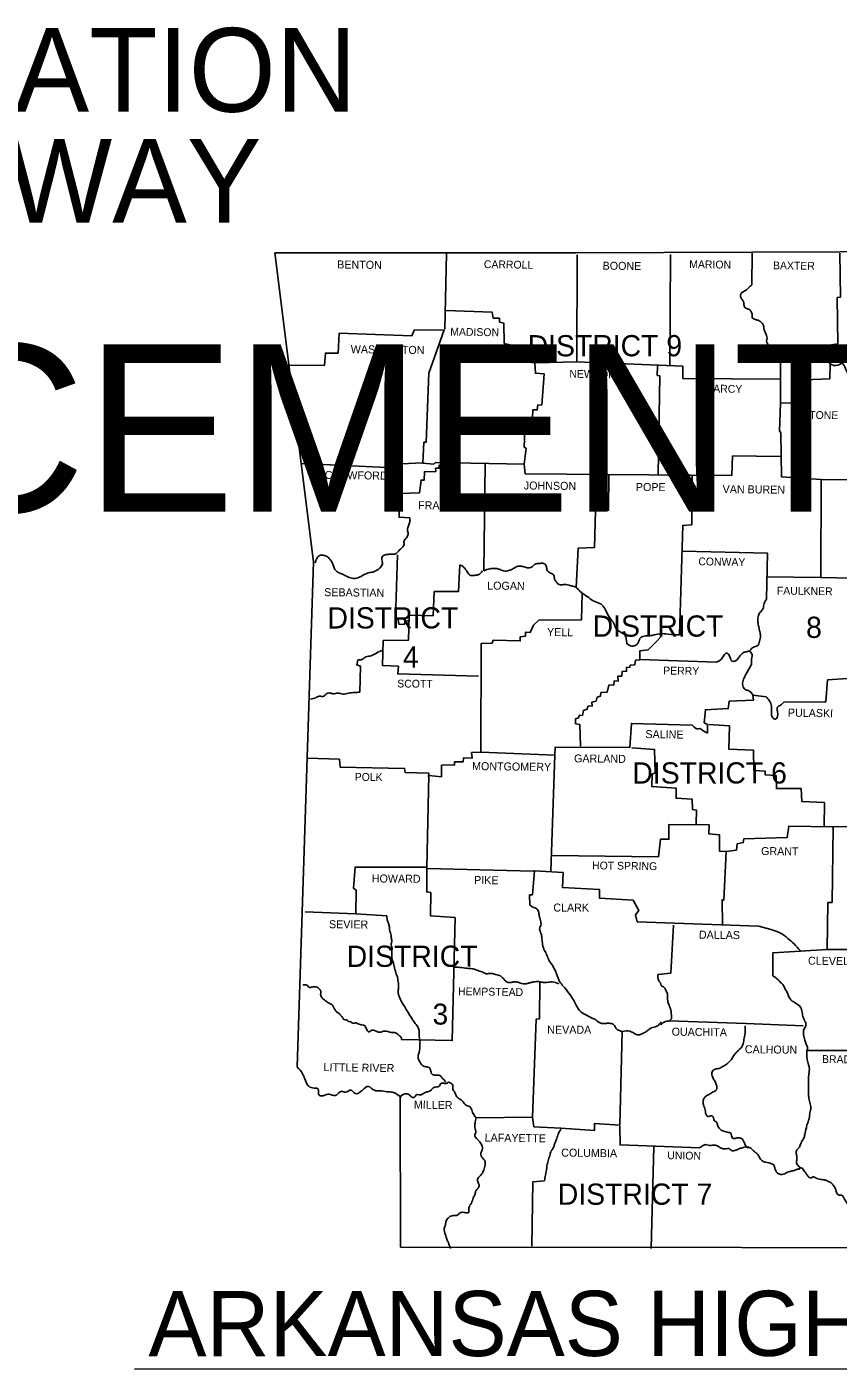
# Model space of a CAD drawing. Extents: x 2520745 to 2582119, y -1491628 to -1461664.
# Drawn here: x 2555441 to 2561979, y -1472575 to -1461753 of the extents above; entities that cross this region are included whole.
import ezdxf

# ---------------------------------------------------------------- set-up
doc = ezdxf.new("R2010")
doc.units = 0
doc.layers.add('R_Draft', color=7, linetype='Continuous')

msp = doc.modelspace()

# ---------------------------------------------------------------- linework, layer by layer
at = {"layer": 'R_Draft'}
msp.add_line((2556309, -1472575), (2566227, -1472569), dxfattribs=at)
for points in [[(2557440, -1463574), (2559865, -1463574), (2561994, -1463568), (2564505, -1463528), (2565669, -1463500)], [(2557619, -1470137), (2557752, -1466067), (2557440, -1463574)], [(2558824, -1463582), (2558811, -1464190)], [(2558821, -1464041), (2559190, -1464053), (2559199, -1464101), (2559250, -1464103), (2559249, -1464133), (2559285, -1464142), (2559288, -1464305), (2559335, -1464316), (2559338, -1464380), (2559404, -1464389), (2559407, -1464449), (2559537, -1464462), (2559873, -1464455), (2559876, -1463592)], [(2560627, -1463589), (2560623, -1464480)], [(2561287, -1463578), (2561284, -1463834)], [(2561541, -1467197), (2561879, -1467196), (2561894, -1467019), (2562095, -1467003), (2562094, -1466199), (2561839, -1466192), (2561843, -1465402), (2561522, -1465381), (2561518, -1465027), (2561507, -1465009), (2561516, -1464787), (2561702, -1464781), (2561709, -1464598), (2561913, -1464590), (2561916, -1464471), (2561880, -1464425), (2561871, -1464325), (2561976, -1464309), (2561971, -1463936), (2561997, -1463934), (2561994, -1463577)], [(2559457, -1465358), (2559449, -1465279), (2558734, -1465265), (2558720, -1465279), (2558632, -1465272), (2558641, -1465103), (2558659, -1465102), (2558682, -1464545), (2558804, -1464197), (2558562, -1464199), (2558544, -1464244), (2557959, -1464223), (2557950, -1464384), (2557847, -1464384), (2557839, -1464483), (2557559, -1464482)], [(2559534, -1464465), (2559540, -1464546), (2559609, -1464551), (2559591, -1464803), (2559560, -1464801), (2559554, -1464842), (2559518, -1464842), (2559516, -1464911), (2559494, -1464912), (2559487, -1465001), (2559454, -1465006), (2559449, -1465141), (2559464, -1465151), (2559449, -1465279)], [(2559873, -1464455), (2560728, -1464490), (2560727, -1464588), (2561511, -1464593)], [(2561516, -1464787), (2561514, -1464449)], [(2560523, -1464486), (2560521, -1464564), (2560541, -1464568), (2560529, -1465360)], [(2561516, -1465217), (2561129, -1465213), (2561122, -1465370), (2559457, -1465358)], [(2557658, -1465274), (2558341, -1465305), (2558344, -1465281), (2558629, -1465267)], [(2558764, -1465285), (2558764, -1465312), (2558735, -1465312), (2558737, -1465339), (2558645, -1465340), (2558644, -1465408), (2558618, -1465408), (2558605, -1465509), (2558443, -1465516), (2558441, -1465707), (2558528, -1465713)], [(2559124, -1466138), (2559134, -1465273)], [(2560130, -1465363), (2560129, -1465650), (2560025, -1465652), (2560017, -1465950), (2559885, -1465955), (2559869, -1466274)], [(2560802, -1465377), (2560799, -1465767), (2560727, -1465773), (2560700, -1466655)], [(2561843, -1465402), (2562614, -1465406), (2562680, -1465374), (2562676, -1465961), (2562631, -1465980), (2562591, -1466015), (2562577, -1466028), (2562576, -1466196), (2562085, -1466196)], [(2560725, -1465981), (2561410, -1465997), (2561401, -1466368)], [(2558931, -1466090), (2558920, -1466305), (2558725, -1466306), (2558715, -1466501), (2558521, -1466497), (2558516, -1466698), (2558313, -1466700), (2558307, -1466901), (2558435, -1466908), (2558430, -1466970), (2559081, -1466987)], [(2558427, -1466010), (2558412, -1466526), (2558434, -1466532), (2558439, -1466568), (2558484, -1466571), (2558488, -1466545), (2558524, -1466539)], [(2561403, -1466186), (2561839, -1466192)], [(2557683, -1468887), (2558092, -1468905), (2558094, -1468713), (2558073, -1468698), (2558086, -1468527), (2558664, -1468528), (2558680, -1467790), (2558782, -1467799), (2558783, -1467707), (2558888, -1467704), (2558887, -1467680), (2558957, -1467680), (2558959, -1467647), (2559031, -1467649), (2559025, -1467604), (2559100, -1467602), (2559102, -1466725), (2559192, -1466722), (2559200, -1466698), (2559417, -1466704), (2559416, -1466672), (2559459, -1466667), (2559461, -1466633), (2559498, -1466636), (2559523, -1466576), (2559568, -1466537), (2559910, -1466535), (2559916, -1466319)], [(2560560, -1466661), (2560506, -1466719), (2560448, -1466775), (2560380, -1466785), (2560380, -1466856), (2560347, -1466860), (2560341, -1466896), (2560304, -1466899), (2560301, -1466916), (2560275, -1466917), (2560274, -1466949), (2560238, -1466951), (2560235, -1466987), (2560205, -1466987), (2560206, -1467029), (2560173, -1467026), (2560172, -1467059), (2560131, -1467062), (2560119, -1467116), (2560068, -1467120), (2560064, -1467150), (2560037, -1467158), (2560029, -1467189), (2559995, -1467197), (2559998, -1467228), (2559963, -1467231), (2559957, -1467255), (2559926, -1467264), (2559918, -1467305), (2559894, -1467303), (2559887, -1467324), (2559864, -1467332), (2559863, -1467372), (2559897, -1467378), (2559904, -1467552)], [(2558126, -1467118), (2558130, -1466907), (2558100, -1466898), (2558109, -1466857)], [(2561000, -1466874), (2560382, -1466854)], [(2560927, -1467447), (2560926, -1467378), (2560899, -1467364), (2560910, -1467259), (2561094, -1467249), (2561100, -1467190), (2561297, -1467182), (2561292, -1467142), (2561400, -1467154)], [(2561871, -1467194), (2561879, -1467187)], [(2559697, -1467624), (2559700, -1467560), (2560300, -1467562), (2560313, -1467369), (2560803, -1467384)], [(2560937, -1467379), (2561105, -1467389), (2561099, -1467577), (2561296, -1467584), (2561299, -1467748), (2561392, -1467755), (2561392, -1467784), (2561479, -1467790), (2561482, -1467895), (2561680, -1467895), (2561686, -1467998), (2561869, -1468007), (2561867, -1468202)], [(2559697, -1467624), (2559100, -1467602)], [(2560318, -1467565), (2560499, -1467579), (2560505, -1467768), (2560480, -1467777), (2560477, -1467877), (2560673, -1467891), (2560673, -1467973), (2560804, -1467981), (2560805, -1468063), (2560837, -1468068), (2560835, -1468179)], [(2557700, -1467650), (2557960, -1467658), (2557966, -1467721), (2558485, -1467732), (2558491, -1467765), (2558680, -1467770), (2558678, -1467799)], [(2559663, -1468559), (2559697, -1467624)], [(2563657, -1468028), (2563090, -1468014), (2563087, -1468198), (2561939, -1468203)], [(2559673, -1468434), (2560531, -1468446), (2560548, -1468303), (2560615, -1468303), (2560616, -1468183), (2560940, -1468188), (2560938, -1468260), (2561022, -1468266), (2561022, -1468398), (2561076, -1468402)], [(2561939, -1468203), (2561581, -1468198), (2561568, -1468289), (2561218, -1468300), (2561215, -1468330), (2561166, -1468339), (2561160, -1468390), (2561076, -1468402)], [(2561939, -1468206), (2561931, -1468812), (2561896, -1468814), (2561892, -1469191)], [(2561076, -1468402), (2561058, -1468795), (2561044, -1468791), (2561046, -1468995)], [(2558664, -1468528), (2558664, -1468727), (2558697, -1468733), (2558694, -1468919), (2558892, -1468934), (2558869, -1469926), (2558461, -1469916)], [(2558667, -1468538), (2559525, -1468560)], [(2559496, -1468835), (2559493, -1468752), (2559517, -1468751), (2559532, -1468557), (2559763, -1468572), (2559757, -1468691), (2560056, -1468707), (2560057, -1468779), (2560327, -1468795), (2560374, -1468876), (2560345, -1468912), (2560359, -1468968), (2561337, -1469003)], [(2558092, -1468905), (2558341, -1468920)], [(2560653, -1468996), (2560631, -1469382), (2560527, -1469394)], [(2561676, -1469204), (2561454, -1469218), (2561453, -1469405)], [(2561673, -1469204), (2561892, -1469191)], [(2561892, -1469191), (2562423, -1469193)], [(2559576, -1469451), (2559573, -1469750), (2559546, -1469753), (2559517, -1470543)], [(2560616, -1469767), (2561237, -1469789), (2561697, -1469807)], [(2559745, -1470633), (2560015, -1470650), (2560016, -1470594), (2560219, -1470608), (2560238, -1469852)], [(2561728, -1470007), (2562406, -1470005)], [(2563950, -1471597), (2558453, -1471591), (2558449, -1470378)], [(2559745, -1470633), (2559527, -1470621), (2559517, -1470543), (2559062, -1470548)], [(2560863, -1470790), (2560222, -1470767), (2560219, -1470615)], [(2560495, -1470780), (2560472, -1471603)], [(2559510, -1471583), (2559520, -1471064), (2559613, -1471058)]]:
    msp.add_lwpolyline(points, dxfattribs=at)
for points in [[(2561284, -1463834), (2561257, -1463857), (2561233, -1463878), (2561197, -1463903), (2561193, -1463927), (2561205, -1463951), (2561217, -1463971), (2561221, -1463998), (2561232, -1464020), (2561257, -1464029), (2561278, -1464049), (2561286, -1464076), (2561289, -1464101), (2561313, -1464113), (2561340, -1464122), (2561365, -1464140), (2561378, -1464163), (2561381, -1464191), (2561391, -1464214), (2561403, -1464241), (2561406, -1464263), (2561403, -1464286), (2561409, -1464307), (2561429, -1464328), (2561463, -1464338), (2561487, -1464353), (2561504, -1464374), (2561493, -1464400), (2561495, -1464422), (2561508, -1464449)], [(2561916, -1464471), (2561976, -1464482), (2562012, -1464468), (2562038, -1464507), (2562051, -1464537), (2562074, -1464581), (2562110, -1464594), (2562137, -1464618), (2562137, -1464644), (2562113, -1464668), (2562095, -1464692), (2562101, -1464720), (2562107, -1464759), (2562107, -1464797), (2562098, -1464831), (2562090, -1464863), (2562098, -1464890), (2562126, -1464885), (2562156, -1464863), (2562188, -1464863), (2562218, -1464879), (2562249, -1464908), (2562281, -1464902), (2562306, -1464894), (2562342, -1464884), (2562368, -1464897), (2562390, -1464915), (2562417, -1464944), (2562443, -1464962), (2562476, -1464978), (2562517, -1464989), (2562554, -1465014), (2562560, -1465058), (2562559, -1465095), (2562556, -1465142), (2562553, -1465193), (2562557, -1465242), (2562574, -1465275), (2562595, -1465314), (2562601, -1465350), (2562599, -1465407)], [(2558528, -1465713), (2558528, -1465744), (2558516, -1465777), (2558509, -1465806), (2558514, -1465843), (2558500, -1465873), (2558481, -1465897), (2558481, -1465927), (2558458, -1465959), (2558434, -1465983), (2558413, -1466002), (2558376, -1466005), (2558344, -1466007), (2558313, -1466017), (2558301, -1466040), (2558307, -1466074), (2558295, -1466107), (2558263, -1466133), (2558229, -1466149), (2558193, -1466155), (2558143, -1466179), (2558098, -1466199), (2558050, -1466196), (2558005, -1466176), (2557965, -1466158), (2557933, -1466140), (2557908, -1466085), (2557891, -1466055), (2557863, -1466025), (2557828, -1466013), (2557800, -1466016), (2557765, -1466075)], [(2558931, -1466090), (2558964, -1466111), (2558989, -1466146), (2559012, -1466174), (2559049, -1466176), (2559079, -1466170), (2559114, -1466140)], [(2559916, -1466319), (2559888, -1466292), (2559858, -1466267), (2559825, -1466259), (2559774, -1466249), (2559741, -1466252), (2559721, -1466243), (2559708, -1466228), (2559694, -1466205), (2559687, -1466174), (2559661, -1466157), (2559633, -1466132), (2559628, -1466105), (2559606, -1466079), (2559574, -1466079), (2559538, -1466085), (2559517, -1466105), (2559481, -1466115), (2559448, -1466107), (2559417, -1466101), (2559384, -1466107), (2559354, -1466126), (2559324, -1466137), (2559283, -1466140), (2559246, -1466125), (2559210, -1466119), (2559174, -1466122), (2559124, -1466138)], [(2559916, -1466319), (2559969, -1466355), (2560018, -1466387), (2560069, -1466409), (2560098, -1466442), (2560123, -1466493), (2560144, -1466525), (2560171, -1466564), (2560191, -1466607), (2560223, -1466631), (2560256, -1466652), (2560272, -1466690), (2560280, -1466727), (2560316, -1466745), (2560350, -1466737), (2560370, -1466715), (2560388, -1466676), (2560428, -1466664), (2560481, -1466659), (2560541, -1466646), (2560607, -1466649), (2560700, -1466655)], [(2561401, -1466368), (2561382, -1466402), (2561373, -1466447), (2561349, -1466476), (2561334, -1466509), (2561332, -1466552), (2561340, -1466591), (2561348, -1466629), (2561354, -1466663), (2561346, -1466707), (2561327, -1466744), (2561297, -1466755), (2561268, -1466780)], [(2558109, -1466857), (2558142, -1466854), (2558174, -1466833), (2558216, -1466824), (2558258, -1466802), (2558310, -1466778)], [(2561000, -1466874), (2561037, -1466853), (2561057, -1466821), (2561081, -1466802), (2561105, -1466828), (2561126, -1466867), (2561148, -1466867), (2561177, -1466840), (2561195, -1466816), (2561217, -1466798), (2561241, -1466791), (2561267, -1466788), (2561286, -1466816), (2561280, -1466861), (2561280, -1466891), (2561264, -1466923), (2561246, -1466956), (2561226, -1466993), (2561211, -1467034), (2561214, -1467073), (2561235, -1467098), (2561259, -1467106), (2561292, -1467139)], [(2558126, -1467118), (2558082, -1467120), (2558033, -1467126), (2557988, -1467132), (2557947, -1467124), (2557910, -1467130), (2557884, -1467124), (2557853, -1467132), (2557835, -1467150), (2557797, -1467150), (2557770, -1467162), (2557727, -1467173)], [(2561400, -1467154), (2561426, -1467187), (2561441, -1467232), (2561441, -1467283), (2561453, -1467325), (2561477, -1467334), (2561492, -1467298), (2561489, -1467262), (2561489, -1467241), (2561514, -1467223), (2561541, -1467197)], [(2560803, -1467384), (2560821, -1467400), (2560841, -1467412), (2560865, -1467411), (2560887, -1467424), (2560927, -1467447)], [(2560238, -1469852), (2560217, -1469846), (2560190, -1469828), (2560175, -1469801), (2560143, -1469787), (2560109, -1469787), (2560062, -1469784), (2560026, -1469759), (2559995, -1469744), (2559945, -1469718), (2559906, -1469694), (2559872, -1469646), (2559849, -1469603), (2559809, -1469544), (2559764, -1469487), (2559735, -1469450), (2559713, -1469394), (2559701, -1469367), (2559675, -1469316), (2559645, -1469270), (2559627, -1469226), (2559608, -1469190), (2559596, -1469138), (2559591, -1469099), (2559586, -1469066), (2559574, -1469018), (2559583, -1468997), (2559580, -1468958), (2559570, -1468920), (2559564, -1468886), (2559549, -1468863), (2559520, -1468850), (2559496, -1468835)], [(2558341, -1468920), (2558349, -1468965), (2558362, -1469004), (2558364, -1469034), (2558378, -1469079), (2558378, -1469095), (2558382, -1469128), (2558376, -1469146), (2558384, -1469182), (2558382, -1469209), (2558382, -1469232), (2558384, -1469269), (2558396, -1469302), (2558408, -1469352), (2558415, -1469377), (2558427, -1469416), (2558435, -1469464), (2558436, -1469500), (2558433, -1469533), (2558442, -1469571), (2558459, -1469608), (2558480, -1469644), (2558505, -1469685), (2558523, -1469716), (2558546, -1469751), (2558564, -1469779), (2558591, -1469815), (2558603, -1469845), (2558603, -1469887), (2558609, -1469926), (2558608, -1469970), (2558605, -1470009), (2558594, -1470063), (2558602, -1470088), (2558630, -1470126), (2558648, -1470136), (2558680, -1470142), (2558695, -1470163), (2558704, -1470194), (2558735, -1470205), (2558770, -1470208), (2558786, -1470226), (2558809, -1470250), (2558816, -1470262)], [(2561337, -1469003), (2561454, -1469036), (2561514, -1469059), (2561574, -1469102), (2561624, -1469146), (2561673, -1469201)], [(2558889, -1469333), (2558946, -1469338), (2558999, -1469344), (2559039, -1469348), (2559081, -1469363), (2559119, -1469377), (2559143, -1469387), (2559183, -1469384), (2559218, -1469392), (2559257, -1469405), (2559285, -1469431), (2559303, -1469450), (2559338, -1469458), (2559366, -1469453), (2559401, -1469456), (2559440, -1469468), (2559471, -1469466), (2559497, -1469460), (2559527, -1469453), (2559564, -1469450), (2559593, -1469456), (2559630, -1469457), (2559674, -1469453), (2559728, -1469468)], [(2560527, -1469394), (2560527, -1469422), (2560538, -1469449), (2560548, -1469461), (2560553, -1469481), (2560566, -1469490), (2560586, -1469508), (2560596, -1469533), (2560604, -1469550), (2560604, -1469571), (2560605, -1469592), (2560608, -1469617), (2560626, -1469662), (2560631, -1469680), (2560634, -1469695), (2560635, -1469721), (2560635, -1469751), (2560616, -1469767)], [(2561453, -1469405), (2561487, -1469428), (2561516, -1469458), (2561537, -1469480), (2561550, -1469506), (2561568, -1469536), (2561594, -1469593), (2561616, -1469612), (2561648, -1469632), (2561667, -1469645), (2561687, -1469689), (2561696, -1469732), (2561712, -1469771), (2561720, -1469801), (2561706, -1469831), (2561703, -1469891), (2561713, -1469932), (2561725, -1469962), (2561732, -1469996), (2561728, -1470007)], [(2557665, -1469480), (2557698, -1469478), (2557721, -1469498), (2557734, -1469496), (2557758, -1469493), (2557781, -1469495), (2557797, -1469508), (2557811, -1469532), (2557809, -1469555), (2557811, -1469564), (2557821, -1469583), (2557839, -1469598), (2557859, -1469613), (2557877, -1469625), (2557907, -1469644), (2557910, -1469650), (2557922, -1469674), (2557937, -1469694), (2557955, -1469706), (2557974, -1469727), (2557983, -1469736), (2557998, -1469757), (2558015, -1469758), (2558037, -1469772), (2558054, -1469776), (2558072, -1469788), (2558090, -1469782), (2558112, -1469791), (2558142, -1469800), (2558159, -1469803), (2558178, -1469832), (2558198, -1469856), (2558222, -1469842), (2558267, -1469856), (2558295, -1469857), (2558321, -1469850), (2558340, -1469851), (2558376, -1469860), (2558399, -1469860), (2558423, -1469869), (2558445, -1469887), (2558461, -1469907), (2558461, -1469916)], [(2560554, -1469775), (2560538, -1469794), (2560518, -1469811), (2560496, -1469818), (2560475, -1469824), (2560448, -1469842), (2560427, -1469857), (2560398, -1469871), (2560371, -1469880), (2560338, -1469869), (2560320, -1469859), (2560301, -1469851), (2560238, -1469852)], [(2560548, -1469799), (2560587, -1469773), (2560631, -1469767)], [(2561231, -1469807), (2561228, -1469882), (2561218, -1469929), (2561207, -1469971), (2561185, -1469995), (2561161, -1470019), (2561138, -1470046), (2561119, -1470079), (2561099, -1470100), (2561074, -1470121), (2561048, -1470136), (2561020, -1470150), (2560988, -1470157), (2560966, -1470174), (2560964, -1470210), (2560990, -1470261), (2560999, -1470285), (2561002, -1470313), (2560991, -1470330), (2560967, -1470343), (2560939, -1470360), (2560913, -1470375), (2560895, -1470400), (2560892, -1470435), (2560904, -1470475), (2560909, -1470499), (2560928, -1470537), (2560943, -1470535), (2560970, -1470537), (2560973, -1470544), (2560975, -1470552), (2560981, -1470571), (2561003, -1470588), (2561006, -1470603), (2561020, -1470631), (2561042, -1470651), (2561059, -1470657), (2561093, -1470667), (2561111, -1470671), (2561131, -1470715), (2561155, -1470713), (2561173, -1470710), (2561203, -1470718), (2561217, -1470736), (2561230, -1470766), (2561248, -1470787), (2561260, -1470787)], [(2561728, -1470007), (2561734, -1470100), (2561747, -1470145), (2561743, -1470193), (2561741, -1470239), (2561741, -1470281), (2561741, -1470322), (2561741, -1470364), (2561744, -1470394), (2561755, -1470437), (2561759, -1470478), (2561750, -1470517), (2561746, -1470553), (2561734, -1470589), (2561723, -1470629), (2561711, -1470682), (2561701, -1470716), (2561680, -1470752), (2561667, -1470785), (2561646, -1470806), (2561643, -1470842), (2561647, -1470875), (2561644, -1470905), (2561655, -1470934), (2561682, -1470953)], [(2558449, -1470378), (2558455, -1470381), (2558426, -1470361), (2558387, -1470342), (2558344, -1470339), (2558288, -1470331), (2558242, -1470327), (2558194, -1470295), (2558143, -1470328), (2558086, -1470352), (2558053, -1470325), (2558009, -1470343), (2557979, -1470334), (2557927, -1470370), (2557877, -1470357), (2557841, -1470367), (2557796, -1470366), (2557787, -1470315), (2557744, -1470308), (2557706, -1470287), (2557681, -1470234), (2557663, -1470194), (2557619, -1470137)], [(2558449, -1470378), (2558501, -1470355), (2558524, -1470363), (2558543, -1470382), (2558566, -1470382), (2558578, -1470364), (2558600, -1470363), (2558618, -1470364), (2558638, -1470352), (2558654, -1470344), (2558677, -1470337), (2558693, -1470331), (2558708, -1470314), (2558735, -1470301), (2558767, -1470290), (2558776, -1470275), (2558791, -1470269), (2558821, -1470271), (2558840, -1470262), (2558857, -1470269), (2558872, -1470280), (2558875, -1470319), (2558887, -1470340), (2558905, -1470377), (2558930, -1470397), (2558954, -1470416), (2558963, -1470428), (2558989, -1470451), (2559011, -1470458), (2559022, -1470475), (2559038, -1470514), (2559062, -1470548)], [(2559062, -1470548), (2559053, -1470592), (2559052, -1470626), (2559059, -1470667), (2559052, -1470686), (2559064, -1470715), (2559087, -1470737), (2559103, -1470761), (2559114, -1470796), (2559100, -1470835), (2559115, -1470875), (2559129, -1470890), (2559136, -1470914), (2559126, -1470961), (2559112, -1470995), (2559082, -1471030), (2559073, -1471046), (2559078, -1471069), (2559085, -1471105), (2559078, -1471115), (2559058, -1471141), (2559052, -1471169), (2559039, -1471193), (2559024, -1471237), (2559004, -1471273), (2559001, -1471313), (2558971, -1471313), (2558937, -1471313), (2558905, -1471336), (2558877, -1471337), (2558842, -1471351), (2558821, -1471379), (2558814, -1471411), (2558805, -1471441), (2558814, -1471492), (2558827, -1471528), (2558838, -1471556), (2558856, -1471603)], [(2559613, -1471058), (2559621, -1471010), (2559628, -1470972), (2559633, -1470936), (2559642, -1470896), (2559655, -1470852), (2559667, -1470816), (2559684, -1470791), (2559694, -1470761), (2559708, -1470725), (2559721, -1470687), (2559745, -1470639)], [(2560863, -1470790), (2560887, -1470774), (2560909, -1470765), (2560932, -1470769), (2560956, -1470772), (2560977, -1470769), (2561004, -1470774), (2561026, -1470787), (2561052, -1470798), (2561077, -1470798), (2561100, -1470797), (2561119, -1470811), (2561155, -1470809), (2561185, -1470797), (2561215, -1470788), (2561256, -1470784), (2561292, -1470809), (2561317, -1470830), (2561338, -1470854), (2561353, -1470881), (2561370, -1470896), (2561397, -1470907), (2561418, -1470911), (2561443, -1470919), (2561457, -1470925), (2561469, -1470953), (2561488, -1470992), (2561526, -1471006), (2561572, -1470988), (2561610, -1470977), (2561637, -1470968), (2561653, -1470962), (2561668, -1470961), (2561664, -1470958), (2561682, -1470953), (2561698, -1470965), (2561709, -1470982), (2561727, -1471006), (2561743, -1471027), (2561760, -1471034), (2561776, -1471025), (2561799, -1471033), (2561818, -1471040), (2561841, -1471046), (2561860, -1471048), (2561886, -1471054), (2561905, -1471064), (2561923, -1471074), (2561941, -1471094), (2561959, -1471124), (2561965, -1471148), (2561986, -1471172), (2562006, -1471172), (2562034, -1471211), (2562045, -1471226), (2562067, -1471253), (2562084, -1471253), (2562115, -1471259)]]:
    msp.add_spline(points, degree=3, dxfattribs=at)

# ---------------------------------------------------------------- texts
for s, height, p in [('ARKANSAS DEPARTMENT OF TRANSPORTATION', 675, (2536635, -1462438)), ('CONSTRUCTION PLANS FOR STATE HIGHWAY', 675, (2536972, -1463332)), ('HWY. 181 DECK REPLACEMENT', 1350, (2534444, -1465663))]:
    msp.add_text(s, height=height, dxfattribs=at).set_placement(p)
for s, height, rotation, p in [('BENTON', 64.5, 359.2876, (2557942, -1463701)), ('CARROLL', 63, 359.183, (2559124, -1463698)), ('BOONE', 64.5, 359.435, (2560081, -1463711)), ('MARION', 63, 359.2204, (2560779, -1463698)), ('BAXTER', 63, 359.2909, (2561454, -1463708)), ('MADISON', 63, 359.1256, (2558853, -1464242)), ('DISTRICT 9', 171, 0.0349, (2559477, -1464410)), ('WASHINGTON', 64.5, 359.2669, (2558051, -1464384)), ('NEWTON', 63, 359.3066, (2559813, -1464582)), ('SEARCY', 63, 359.2876, (2560860, -1464700)), ('STONE', 63, 359.435, (2561690, -1464913)), ('CRAWFORD', 64.5, 359.312, (2557841, -1465398)), ('JOHNSON', 64.5, 359.3863, (2559446, -1465483)), ('POPE', 64.5, 359.6504, (2560349, -1465495)), ('VAN BUREN', 64.5, 359.3857, (2561048, -1465512)), ('FRANKLIN', 64.5, 359.2165, (2558594, -1465642)), ('CONWAY', 63, 359.0721, (2560852, -1466094)), ('SEBASTIAN', 64.5, 359.3165, (2557837, -1466343)), ('LOGAN', 64.5, 359.4318, (2559151, -1466290)), ('FAULKNER', 63, 359.2836, (2561485, -1466330)), ('DISTRICT', 171, 0.0349, (2557864, -1466604)), ('DISTRICT', 171, 0.0349, (2560001, -1466670)), ('8', 171, 0.0349, (2561721, -1466680)), ('YELL', 64.5, 359.2337, (2559633, -1466664)), ('4', 171, 0.0349, (2558472, -1466919)), ('PERRY', 63, 359.1207, (2560569, -1466974)), ('SCOTT', 63, 359.4412, (2558426, -1467079)), ('PULASKI', 64.5, 359.088, (2561574, -1467314)), ('SALINE', 64.5, 359.1841, (2560426, -1467487)), ('MONTGOMERY', 64.5, 359.3294, (2559029, -1467745)), ('GARLAND', 64.5, 359.4007, (2559851, -1467683)), ('DISTRICT 6', 171, 0.0349, (2560321, -1467854)), ('POLK', 63, 359.2501, (2558083, -1467831)), ('GRANT', 64.5, 359.4381, (2561358, -1468430)), ('HOT SPRING', 63, 359.2565, (2559996, -1468545)), ('HOWARD', 64.5, 359.5494, (2558221, -1468651)), ('PIKE', 64.5, 359.0801, (2559045, -1468663)), ('CLARK', 64.5, 0.0349, (2559684, -1468886)), ('SEVIER', 64.5, 359.462, (2557876, -1469020)), ('DALLAS', 64.5, 359.2811, (2560857, -1469104)), ('DISTRICT', 171, 0.0349, (2558019, -1469332)), ('CLEVELAND', 64.5, 359.3726, (2561736, -1469314)), ('HEMPSTEAD', 63, 359.2234, (2558916, -1469560)), ('3', 169, 0.0349, (2558711, -1469797)), ('NEVADA', 64.5, 0.0349, (2559635, -1469871)), ('OUACHITA', 64.5, 359.2392, (2560637, -1469886)), ('CALHOUN', 64.5, 359.3983, (2561227, -1470028)), ('BRADLEY', 63, 359.1798, (2561849, -1470106)), ('LITTLE RIVER', 64.51, 359.2046, (2557832, -1470172)), ('MILLER', 64.5, 359.1669, (2558560, -1470474)), ('LAFAYETTE', 64.5, 359.2188, (2559130, -1470740)), ('COLUMBIA', 64.5, 359.2474, (2559747, -1470861)), ('UNION', 63, 358.9933, (2560602, -1470882)), ('DISTRICT 7', 171, 0.0349, (2559720, -1471250)), ('ARKANSAS HIGHWAY DISTRICT 10', 525, 0.0349, (2556421, -1472471))]:
    msp.add_text(s, height=height, rotation=rotation, dxfattribs=at).set_placement(p)

doc.saveas('drawing.dxf')
